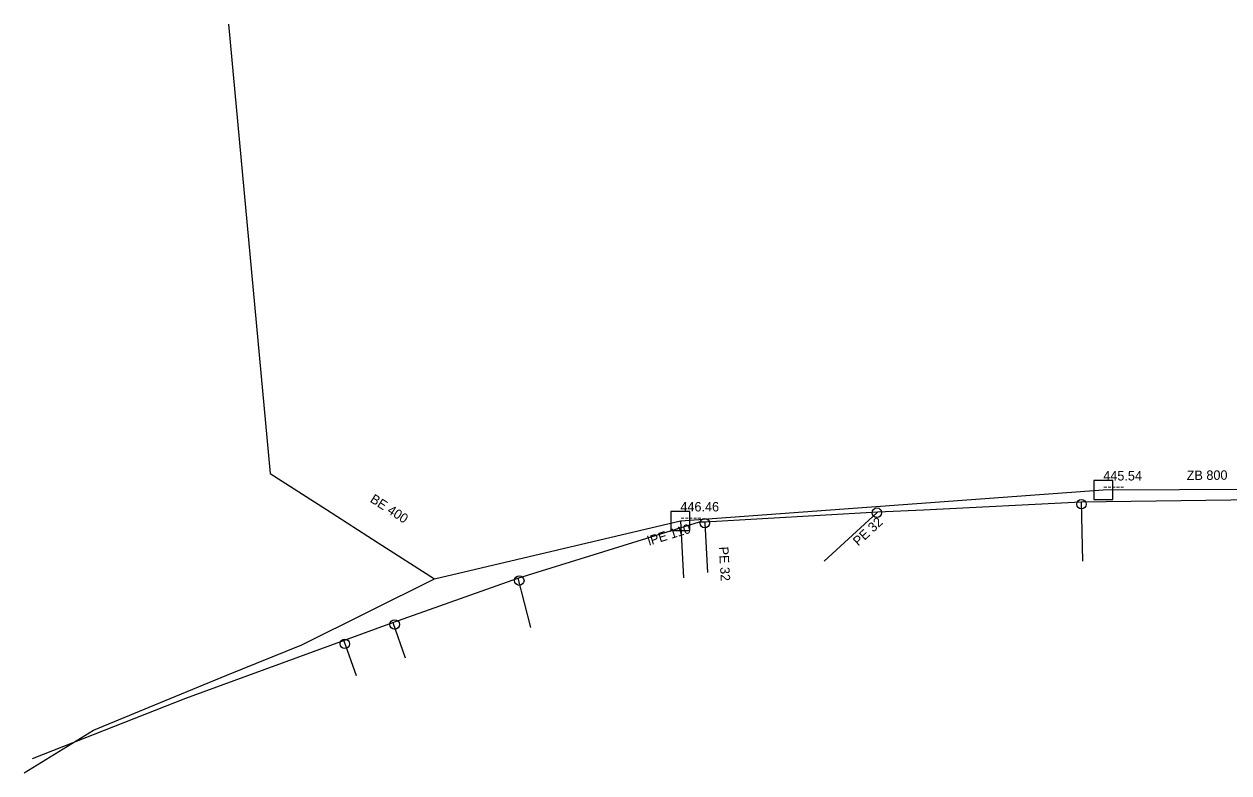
# Model space of a CAD drawing. Extents: x -756595 to -756146, y -1112266 to -1111946.
# Drawn here: x -756595.5 to -756468, y -1112036.2 to -1111957.1 of the extents above; entities that cross this region are included whole.
import ezdxf

# ---------------------------------------------------------------- set-up
doc = ezdxf.new("R2010")
doc.units = 0
doc.layers.add('Level 0', color=7, linetype='Continuous')

msp = doc.modelspace()

# ---------------------------------------------------------------- linework, layer by layer
at = {"layer": 'Level 0'}
for p, q in [((-756573.851, -1111957.085), (-756569.42, -1112004.58)), ((-756569.42, -1112004.58), (-756563.47, -1112008.39)), ((-756526.05, -1112009.59), (-756481.33, -1112006.32)), ((-756480.33, -1112005.32), (-756482.33, -1112005.32)), ((-756482.33, -1112005.32), (-756482.33, -1112007.32)), ((-756481.33, -1112006.32), (-756463.65, -1112006.21)), ((-756480.33, -1112007.32), (-756480.33, -1112005.32)), ((-756500.35, -1112008.41), (-756483.65, -1112007.57)), ((-756483.65, -1112007.57), (-756447.44, -1112007.09)), ((-756483.65, -1112007.57), (-756483.53, -1112013.86)), ((-756482.33, -1112007.32), (-756480.33, -1112007.32)), ((-756563.47, -1112008.39), (-756558, -1112011.9)), ((-756525.05, -1112008.59), (-756527.05, -1112008.59)), ((-756527.05, -1112008.59), (-756527.05, -1112010.59)), ((-756525.05, -1112010.59), (-756525.05, -1112008.59)), ((-756523.48, -1112009.67), (-756505.16, -1112008.62)), ((-756505.27, -1112008.72), (-756510.83, -1112013.84)), ((-756505.16, -1112008.62), (-756505.27, -1112008.72)), ((-756505.16, -1112008.62), (-756500.35, -1112008.41)), ((-756552.05, -1112015.72), (-756526.05, -1112009.59)), ((-756543.23, -1112015.64), (-756524.04, -1112009.7)), ((-756526.05, -1112009.59), (-756525.73, -1112015.6)), ((-756524.04, -1112009.7), (-756523.48, -1112009.67)), ((-756523.48, -1112009.67), (-756523.47, -1112009.82)), ((-756523.47, -1112009.82), (-756523.17, -1112015.03)), ((-756527.05, -1112010.59), (-756525.05, -1112010.59)), ((-756558, -1112011.9), (-756552.05, -1112015.72)), ((-756566.09, -1112022.68), (-756552.05, -1112015.72)), ((-756556.45, -1112020.34), (-756543.23, -1112015.64)), ((-756543.23, -1112015.64), (-756541.89, -1112020.87)), ((-756578.35, -1112028.31), (-756556.45, -1112020.34)), ((-756556.45, -1112020.34), (-756555.15, -1112024.05)), ((-756574.02, -1112025.89), (-756566.09, -1112022.68)), ((-756561.66, -1112022.27), (-756560.35, -1112025.94)), ((-756580.02, -1112028.37), (-756574.02, -1112025.89)), ((-756594.58, -1112034.71), (-756578.35, -1112028.31)), ((-756588.12, -1112031.72), (-756580.02, -1112028.37)), ((-756595.46, -1112036.22), (-756588.12, -1112031.72))]:
    msp.add_line(p, q, dxfattribs=at)
for centre in [(-756483.64, -1112007.82), (-756505.27, -1112008.72), (-756523.47, -1112009.82), (-756543.09, -1112015.9), (-756556.27, -1112020.53), (-756561.54, -1112022.58)]:
    msp.add_circle(centre, 0.5, dxfattribs=at)

# ---------------------------------------------------------------- texts
for s, p in [('445.54', (-756481.33, -1112005.32)), ('-----', (-756481.33, -1112006.42)), ('446.46', (-756526.05, -1112008.59)), ('-----', (-756526.05, -1112009.69))]:
    msp.add_text(s, height=1, dxfattribs=at).set_placement(p)
for s, rotation, p in [('ZB 800', 0.356, (-756472.5, -1112005.27)), ('BE 400', 327.312, (-756558.95, -1112007.53)), ('lPE 110', 17.199, (-756529.35, -1112012.21)), ('PE 32', 42.641, (-756507.24, -1112012.3)), ('PE 32', 273.296, (-756521.98, -1112012.34))]:
    msp.add_text(s, height=1, rotation=rotation, dxfattribs=at).set_placement(p)

doc.saveas('drawing.dxf')
